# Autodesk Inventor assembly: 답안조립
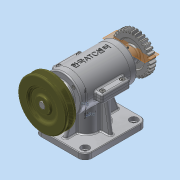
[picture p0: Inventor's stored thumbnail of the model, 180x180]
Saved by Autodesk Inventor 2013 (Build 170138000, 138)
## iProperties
Created: 2015-09
Part Number: 답안조립
Document SubType Name: Assembly
Designer: Administrator
Author: Administrator
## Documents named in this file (17)
- C:\Users\Administrator\Desktop\350908V1011\답안조립.iam
- C:\Users\Administrator\Desktop\350908V1011\M3x0.5x8.ipt
- C:\Users\Administrator\Desktop\350908V1011\M4x0.5x14.ipt
- C:\Users\Administrator\Desktop\350908V1011\V-벨트풀리.ipt
- C:\Users\Administrator\Desktop\350908V1011\뒤커버.ipt
- C:\Users\Administrator\Desktop\350908V1011\멈춤나사.ipt
- C:\Users\Administrator\Desktop\350908V1011\베어링 6201.ipt
- C:\Users\Administrator\Desktop\350908V1011\베어링 6202.ipt
- C:\Users\Administrator\Desktop\350908V1011\본체 커버.ipt
- C:\Users\Administrator\Desktop\350908V1011\본체.ipt
- C:\Users\Administrator\Desktop\350908V1011\스퍼기어.ipt
- C:\Users\Administrator\Desktop\350908V1011\스프링 - [가변].ipt
- C:\Users\Administrator\Desktop\350908V1011\슬라이드.ipt
- C:\Users\Administrator\Desktop\350908V1011\앞커버.ipt
- C:\Users\Administrator\Desktop\350908V1011\오일실.ipt
- C:\Users\Administrator\Desktop\350908V1011\키4x4.ipt
- C:\Users\Administrator\Desktop\350908V1011\편심축.ipt
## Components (13 placed, 3 different names)
1. M4x0.5x14:1
2. V-벨트풀리:1 — 플러쉬:3
3. M4x0.5x14:2
4. M4x0.5x14:3
5. M4x0.5x14:4
6. M3x0.5x8:1
7. M3x0.5x8:3
8. M3x0.5x8:4
9. M3x0.5x8:5
10. M3x0.5x8:2
11. M3x0.5x8:6
12. M3x0.5x8:7
13. M3x0.5x8:8
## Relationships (1: Flush 1)
- 플러쉬:3 [Flush]: V-벨트풀리:1
